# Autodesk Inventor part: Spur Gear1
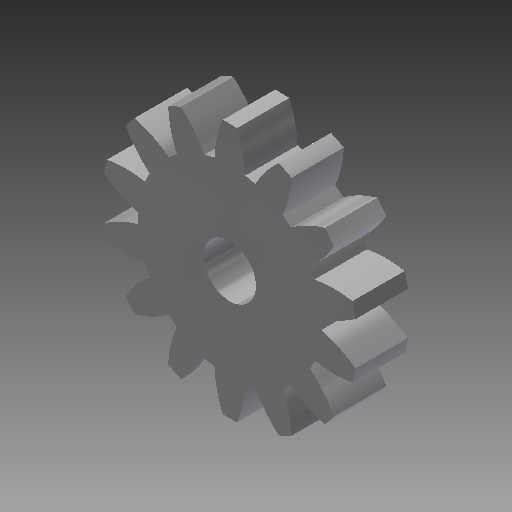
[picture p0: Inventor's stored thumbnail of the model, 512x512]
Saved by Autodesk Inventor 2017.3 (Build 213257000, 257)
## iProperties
Created: 2020-03
Part Number: Spur Gear1
Material: Steel
Document SubType Name: Modeling
Designer: Tim_G
Categories: <?xml version="1.0" encoding="UTF-16"?> <MemberInstance><Categories><FamilyTemplate><FamilyTemplateParameter ValueType="xs:double" Id="1" ObjectReferenceKey="da
Density: 1 g/cm^3
Appearance: Steel
CustomPartVersion: 1
Author: Tim_G
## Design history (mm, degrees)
sketch "Sketch1"
  geometry: C1 r 12.183 at (0, 0)
  constraints: 1 centre point
  dimensions: "d0" = 24.36697 diameter of C1 (= da_da)
extrude "Extrusion1" new body sketch "Sketch1" distance "d1" = 5 (= da_b); taper "d2" = 0 deg
workplane "Work Plane2"
sketch "Sketch2"
  geometry: C1 r 12.183 at (0, 0) reference; C2 r 10.661 at (0, 0)
  constraints: 1 centre point, 1 coincident
  dimensions: "d3" = 21.3211 diameter of C2 (= da_dw)
feature "Pitch Diameter" sketch "Sketch2" dims "d4" = 10, "d5" = 0
workplane "Work Plane8"
workplane "Work Plane9"
feature "Spur Gear" dims "da_b" = 5, "da_d" = 21.3211, "da_aw" = 25.12844, "da_da" = 24.36697, "da_df" = 17.51376, "da_dw" = 21.3211, angle "da_beta" = 0 deg, "da_lefttooth" = 0, "da_righttooth" = 0
sketch "Sketch3"
  geometry: C1 r 2.5 at (0, 0); 1 further point
  constraints: 1 centre point, 1 coincident
  dimensions: "d49" = 5 diameter of C1
extrude "Extrusion2" cut sketch "Sketch3" distance "d50" = 5; taper "d51" = 0 deg
body "Solid1"
body "Srf1"
other parameters: "d16" = 25.12844 (= da_aw), "d17" = 0, "d34" = 2.24399 (computed from da_z), "d39" = 0, "d41" = 0, "d43" = 25.12844 (= da_aw), "d46" = 25.12844 (= da_aw), "d47" = 0, "d48" = 0
